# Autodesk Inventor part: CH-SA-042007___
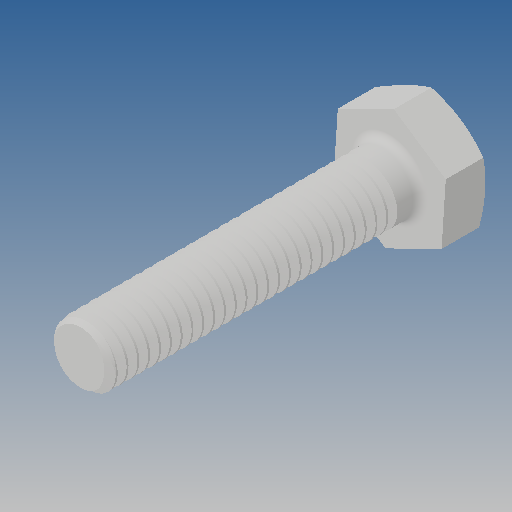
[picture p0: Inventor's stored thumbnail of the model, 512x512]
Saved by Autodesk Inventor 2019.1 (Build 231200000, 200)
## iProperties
Created: 2010-06
Part Number: CH-SA-042007___
Material: Ogólny
Document SubType Name: Modeling
Designer: CADENGINEERING4
Density: 1 g/cm^3
Appearance: Domyślna
Author: CADENGINEERING4
Revision Number: ANY
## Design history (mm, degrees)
feature "NONE"
node "Bryła1"
